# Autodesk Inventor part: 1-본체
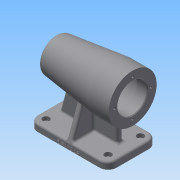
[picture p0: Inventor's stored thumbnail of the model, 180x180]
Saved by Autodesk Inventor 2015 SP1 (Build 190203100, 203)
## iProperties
Created: 2018-09
Part Number: 1-본체
Material: Generic
Document SubType Name: Modeling
Designer: Administrator
Density: 1 g/cm^3
Appearance: Default
Author: Administrator
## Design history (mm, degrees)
sketch "스케치1"
  geometry: L1 (-56, 35)-(56, 35); L2 (56, 35)-(56, -35); L3 (56, -35)-(-56, -35); L4 (-56, -35)-(-56, 35); L5 (-56, 35)-(56, -35); L6 (56, 35)-(-56, -35); 1 further point
  constraints: 12 end point, 2 midpoint, 2 parallel, 1 horizontal, 1 perpendicular
  dimensions: "d0" = 112 distance of L1.start L1.end; "d1" = 70 distance of L1.end L2.end
extrude "돌출1" new body sketch "스케치1" distance "d2" = 10; taper "d3" = 0 deg
fillet "모깎기1" dims "d4" = 12
hole "구멍1" diameter "d7" = 5.5; stored, may be unused: countersink angle "d11" = 90 deg, drill point angle "d13" = 0 deg; dims "d5" = 10, "d6" = 10, "d8" = 6, "d9" = 9.5, "d10" = 5.4, "d12" = 8
hole "구멍2" diameter "d16" = 5.5; stored, may be unused: countersink angle "d20" = 90 deg, drill point angle "d22" = 0 deg; dims "d14" = 10, "d15" = 10, "d17" = 6, "d18" = 9.5, "d19" = 5.4, "d21" = 8
hole "구멍3" diameter "d25" = 5.5; stored, may be unused: countersink angle "d29" = 90 deg, drill point angle "d31" = 0 deg; dims "d23" = 10, "d24" = 10, "d26" = 6, "d27" = 9.5, "d28" = 5.4, "d30" = 8
hole "구멍4" diameter "d34" = 5.5; stored, may be unused: countersink angle "d38" = 90 deg, drill point angle "d40" = 0 deg; dims "d32" = 10, "d33" = 10, "d35" = 6, "d36" = 9.5, "d37" = 5.4, "d39" = 8
node "작업 평면1"
sketch "스케치2"
  geometry: L1 (-12, 74)-(100, 74); L2 (0, 0)-(88, 0) reference; L3 (0, 0)-(-12, 0) reference; L4 (100, 0)-(88, 0) reference; L5 (88, 0)-(88, 10) reference; L6 (0, 0)-(88, 0) reference; L7 (0, 10)-(0, 0) reference; L8 (88, 10)-(0, 10) reference; L9 (100, 74)-(100, 108); L10 (100, 108)-(72, 108); L11 (72, 108)-(-8.27, 98.144); L12 (100, 95)-(85, 95); L13 (85, 95)-(85, 98); L14 (85, 98)-(31, 98); L15 (31, 98)-(31, 95); L16 (31, 95)-(19, 95); L17 (19, 95)-(19, 91.5); L18 (19, 91.5)-(1, 91.5); L19 (1, 91.5)-(1, 90); L20 (1, 90)-(-3, 90); L21 (-3, 90)-(-3, 84.5); L22 (-3, 84.5)-(-6, 84.5); L23 (-6, 84.5)-(-6, 74); A1 r 80 centre (68, 74) between (-8.27, 98.144) and (-12, 74); 3 further points
  constraints: 32 end point, 11 perpendicular, 5 point on line, 2 horizontal, 2 midpoint, 2 point on circle, 1 centre point, 1 vertical, 1 vertical alignment
  dimensions: "d41" = 74 distance between parallel lines of L2 L1; "d42" = 28 distance of L9.end L10.end; "d43" = 68 diameter of L10 L1; "d44" = 112 distance of L1.start L1.end; "d45" = 7 deg angle of L10 L11; "d47" = 48 diameter of L14 L1; "d48" = 42 diameter of L16 L1; "d49" = 35 diameter of L18 L1; "d50" = 32 diameter of L20 L1; "d51" = 21 diameter of L22 L1; "d52" = 54 distance of L13.end L14.end; "d53" = 15 distance of L12.start L12.end; "d54" = 12 distance of L15.end L16.end; "d55" = 18 distance of L17.end L18.end; "d56" = 4 distance of L19.end L20.end; "d57" = 3 distance of L21.end L22.end; "d95" = 80 radius of A1
  node "투영된 루프1"
revolve "회전1" stored, may be unused: angle "d46" = 90 deg
sketch "스케치3"
  geometry: L1 (88, 0)-(88, 10) reference; L2 (0, 0)-(88, 0) reference; L3 (0, 10)-(0, 0) reference; L4 (88, 10)-(0, 10) reference; L5 (82, 10)-(82, 78.547); L6 (82, 78.547)-(18.367, 78.547); L7 (18.367, 78.547)-(0, 10); L8 (0, 10)-(82, 10); L9 (100, 10)-(100, 0) reference; L10 (-12, 0)-(-12, 10) reference; L11 (-12, 10)-(0, 10) reference; 1 further point
  constraints: 8 end point, 2 perpendicular, 1 parallel, 1 point on line
  dimensions: "d58" = 18 distance between parallel lines of L9 L5; "d59" = 105 deg angle of L7 L11; "d60" = 63.63282 distance of L5.end L6.end
extrude "돌출2" join sketch "스케치3" stored distance "d61" = 8; taper "d62" = 0 deg
node "작업 평면2"
fillet "모깎기6" dims "d85" = 3
sketch "스케치4"
  geometry: L1 (7, 46)-(0, 46) reference; L2 (0, 46)-(0, 58) reference; L3 (0, 58)-(7, 58) reference; L4 (10, 58)-(10, 46) reference; L5 (10, -12)-(0, -12) reference; L6 (7, 46)-(7, 58) reference; L7 (10, 55)-(10, 46) reference; L8 (10, 46)-(10, 0) reference; L9 (10, 0)-(10, -9) reference; L10 (8.026, -11.819)-(69.675, 10.619); L11 (69.675, 10.619)-(69.675, 35.381); L12 (69.675, 35.381)-(8.026, 57.819); A1 r 3 centre (7, 55) between (10, 55) and (7, 58) reference; A2 r 3 centre (7, -9) between (7, -12) and (10, -9) reference; 1 further point
  constraints: 6 end point, 2 point on circle, 2 tangent, 1 vertical
  dimensions: "d86" = 20 deg angle of L5 L10; "d87" = 20 deg angle of L12 L3; "d88" = 24.76131 distance of L10.end L11.end
extrude "돌출3" join sketch "스케치4" stored distance "d66" = 8; taper "d67" = 0 deg
revolve "회전2" stored, may be unused: angle "d68" = 90 deg
sketch "스케치6"
  geometry: L1 (100, 0)-(100, 10) reference; L2 (88, 0)-(0, 0) reference; 2 further points
  constraints: 1 other
  dimensions: "d77" = 56 distance from line of L1 point (44, 3); "d78" = 3 distance from line of point (44, 3) L2
feature "엠보싱1" sketch "스케치6" dims "d0" = 112, "d1" = 70, "d25" = 5.5, "d79" = 0.5, "d80" = 0
fillet "모깎기3" dims "d82" = 3
fillet "모깎기4" dims "d83" = 3
fillet "모깎기7" dims "d89" = 3
chamfer "모따기1" distance "d90" = 1; stored, may be unused: second distance "d91" = 2, angle "d92" = 45 deg
fillet "모깎기10" dims "d96" = 3
fillet "모깎기11" dims "d97" = 3, "d98" = 0.3
sketch "스케치7"
  geometry: C1 r 34 at (0, 0) reference; C2 r 22 at (0, 0) reference; A1 r 26 centre (0, 0) between (-26, 0) and (0, -26); 3 further points
  constraints: 4 point on circle, 2 horizontal alignment, 2 vertical alignment, 1 centre point, 1 coincident
  dimensions: "d99" = 52 diameter of A1
hole "구멍6" sketch "스케치7" at (-26, 0), (0, -26), (26, 0), (0, 26) diameter "d100" = 3.242; stored, may be unused: countersink angle "d104" = 90 deg, drill point angle "d106" = 118 deg; dims "d101" = 8, "d102" = 9.5, "d103" = 5.4, "d105" = 11
fillet "모깎기12" dims "d107" = 3
node "솔리드1"
node "투영된 루프2"
node "투영된 루프3"
node "투영된 루프5"
